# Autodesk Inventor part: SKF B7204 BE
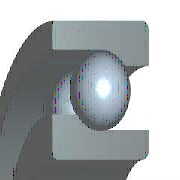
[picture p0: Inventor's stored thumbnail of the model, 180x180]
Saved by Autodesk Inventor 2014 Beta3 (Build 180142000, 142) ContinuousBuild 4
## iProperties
Created: 2010-11
Part Number: SKF B7204 BE
Material: Steel, Mild
Description: Single row angular contact ball bearings SKF
Document SubType Name: Modeling
Standard: SKF B
Designer: Beta-8540w
Language: en-US
Size Designation: SKF B7204 BE
Categories: <MemberInstance><Categories><Category DisplayName="Shaft Parts" InternalName="7f7aeb1f-a693-4053-b835-cee3144e0d98" Mnemonic="SHFT"><Category DisplayName="Beari
Density: 7.86 g/cm^3
Appearance: Steel
IsCustomPart: 0
Author: Beta-8540w
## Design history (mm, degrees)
node "WorkPlane1"
workplane "Work Plane2"
node "WorkPlane2"
node "Sketch1"
node "WorkPoint1"
node "Sketch2"
node "WorkPoint3"
node "Sketch3"
node "WorkPoint2"
node "WorkAxis1"
node "Sketch7"
workaxis "Work Axis2"
pattern_circular "PolarArray1" dims angle "d18" = 360 deg
fillet "Fillet1" dims "d19" = 0.6 (= r1)
fillet "Fillet2" dims "d20" = 1 (= r)
body "Solid1"
revolve "Revolution1" stored, may be unused: angle "d7" = 360 deg
revolve "Revolution2" stored, may be unused: angle "d12" = 360 deg
revolve "Revolution3" stored, may be unused: angle "d15" = 360 deg
sketch "Sketch4"
  geometry: L1 (23.5, 0)-(10, 0); L2 (23.5, 14)-(23.5, 0); L3 (10, 14)-(23.5, 14); L4 (10, 0)-(10, 14); L5 (0, -3.737)-(0, 15.931); L6 (0, -3.737)-(0, 15.931); L7 (0, -7.671)-(0, 19.865) reference; L8 (-4.7, 0)-(28.2, 0) reference
  constraints: 12 end point, 3 vertical, 2 collinear, 2 horizontal
  dimensions: "d2" = 10 horizontal distance of L3.start L5.end (= 0.5 x Diam); "d4" = 23.5 horizontal distance of L2.start L5.end (= 0.5 x DD); "d6" = 14 distance of L1.end L3.start (= B)
sketch "Sketch5"
  geometry: L1 (20.8, 14)-(14.32, 14); L2 (20.8, 7)-(20.8, 14); L3 (19.18, 0)-(19.18, 3.76); L4 (12.7, 0)-(19.18, 0); L5 (12.7, 7)-(12.7, 0); L6 (14.32, 14)-(14.32, 10.24); L7 (23.5, 0)-(-23.5, 0) reference; L8 (23.5, 14)-(-23.5, 14) reference; L9 (0, 40.963)-(0, -26.963); L10 (0, -40.549)-(0, 54.549) reference; A1 r 4.05 centre (16.75, 7) between (19.18, 3.76) and (20.8, 7); A2 r 4.05 centre (16.75, 7) between (14.32, 10.24) and (12.7, 7); A3 r 4.05 centre (16.75, 7) between (20.8, 7) and (14.32, 10.24)
  constraints: 14 end point, 7 point on circle, 4 vertical, 3 centre point, 3 collinear, 2 horizontal, 2 tangent, 1 coincident, 1 concentric
  dimensions: "d9" = 7 vertical distance of A2.centre L3.start (= 0.5 x B); "d11" = 8.1 diameter of A3 (= msp_mdtdk); "d21" = 33.5 diameter of A1.centre L9 (= msp_mdtds); "d22" = 28.64 diameter of L6 L9 (= msp_md); "d23" = 38.36 diameter of L3 L9 (= msp_vd)
sketch "Sketch6"
  geometry: L1 (16.75, 2.95)-(16.75, 11.05); L2 (16.75, 15.175)-(16.75, -1.013); L3 (23.5, 0)-(-23.5, 0) reference; L4 (16.75, 15.175)-(16.75, -1.013); L5 (20.8, 7)-(-20.8, 7) reference; A1 r 4.05 centre (16.75, 7) between (16.75, 2.95) and (16.75, 11.05); A2 r 4.05 centre (16.75, 7) between (14.32, 10.24) and (12.7, 7) reference
  constraints: 6 end point, 4 point on line, 2 point on circle, 1 centre point, 1 concentric, 1 vertical
  dimensions: "d14" = 4.05 radius of A1 (= 0.5 x msp_mdtdk)
other parameters: "DD" = 47 [user parameter; used in 3 equation terms], "B" = 14 [user parameter; used in 3 equation terms], "r" = 1 [user parameter; used in 1 equation term], "msp_mdtdk" = 8.1 (= -0.3 x Diam + 0.3 x DD) [user parameter; used in 5 equation terms], "msp_mdtds" = 33.5 (= 0.5 x DD + 0.5 x Diam) [user parameter; used in 4 equation terms], "msp_md" = 28.64 (= msp_mdtds - 0.6 x msp_mdtdk) [user parameter; used in 1 equation term], "msp_vd" = 38.36 (= msp_mdtds + 0.6 x msp_mdtdk) [user parameter; used in 1 equation term], "r1" = 0.6 [user parameter; used in 1 equation term], "d0" = -14 (computed from B), "d3" = 23.5 (derived), "d5" = 14 (derived), "d8" = 7 (derived), "d10" = 8.1 (derived), "d13" = 4.05 (derived), "d26" = 0, "d27" = 0, "d28" = 0, "d29" = 0, "d30" = 0
